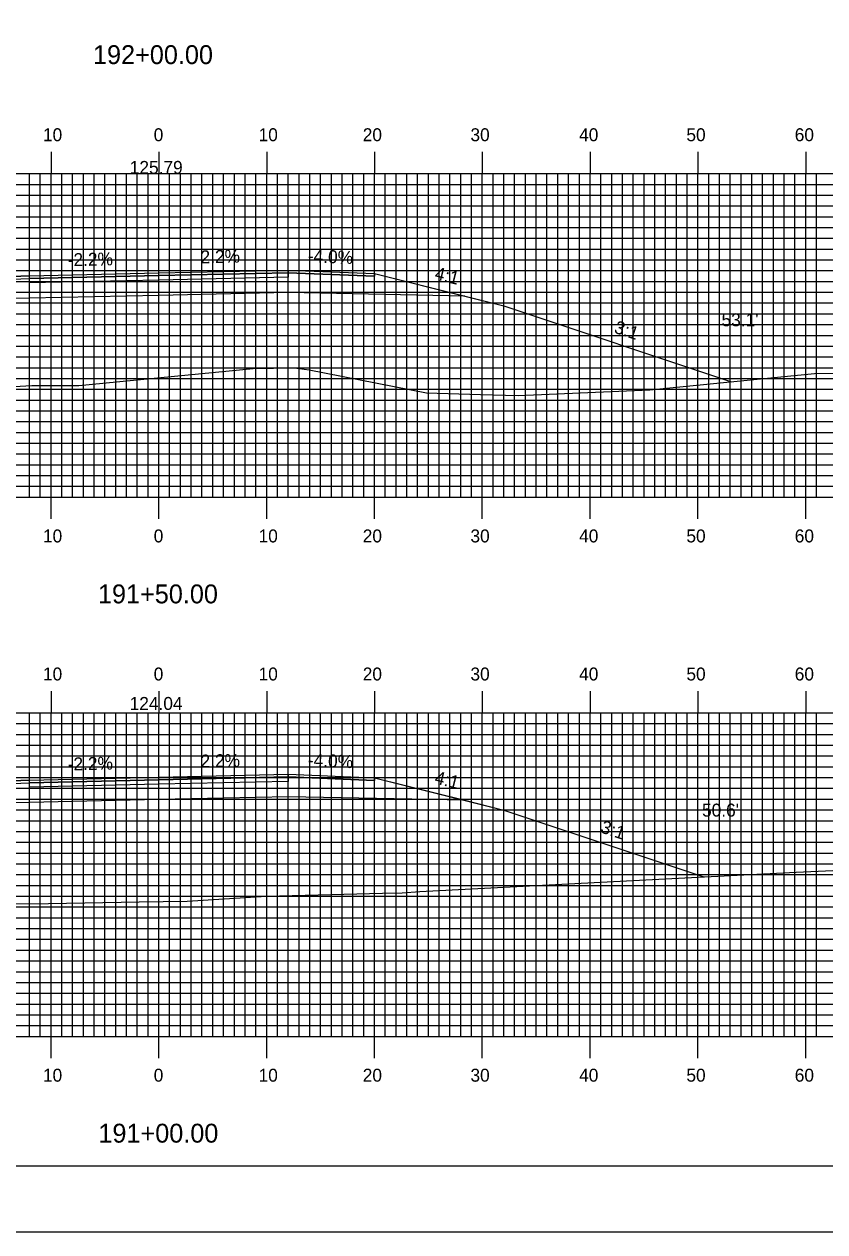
# Model space of a CAD drawing. Extents: x 1788550 to 1788893, y 442591 to 442811.
# Drawn here: x 1788703.1 to 1788777.4, y 442590.5 to 442702.5 of the extents above; entities that cross this region are included whole.
import ezdxf

# ---------------------------------------------------------------- set-up
doc = ezdxf.new("R2010")
doc.units = 0
for name, color, linetype in [('ANNOTATION', 7, 'Continuous'), ('BORDER', 7, 'Continuous'), ('D_Roadway_Centerline', 7, 'Continuous'), ('D_Roadway_Centerline_Text', 7, 'Continuous'), ('D_Roadway_Edge_Shoulder', 7, 'Continuous'), ('D_Roadway_Edge_TW', 7, 'Continuous'), ('D_Roadway_Pavement', 7, 'Continuous'), ('D_Roadway_SlopeLines', 7, 'Continuous'), ('D_Roadway_SubGrade', 7, 'Continuous'), ('D_Text_Standard', 7, 'Continuous'), ('H_V ANNOTATION', 7, 'Continuous'), ('MAJOR', 7, 'Continuous'), ('MINOR', 7, 'Continuous'), ('PLOT BOUNDARY', 7, 'Continuous'), ('S_Roadway_Centerline', 7, 'Continuous')]:
    doc.layers.add(name, color=color, linetype=linetype)

msp = doc.modelspace()

# ---------------------------------------------------------------- linework, layer by layer
at = {"layer": 'BORDER'}
msp.add_lwpolyline([(1788566.04, 442596.67), (1788886.04, 442596.67), (1788886.04, 442806.67), (1788566.04, 442806.67)], close=True, dxfattribs=at)
at = {"layer": 'D_Roadway_Centerline'}
for points in [[(1788655.04, 442666.34), (1788683.64, 442675.87), (1788687.28, 442676.78), (1788695.64, 442678.87), (1788703.64, 442679.19), (1788715.64, 442679.46), (1788727.64, 442679.72), (1788735.64, 442679.4), (1788744.01, 442677.31), (1788747.64, 442676.4), (1788768.74, 442669.37)], [(1788655.7, 442619.81), (1788683.64, 442629.12), (1788687.28, 442630.03), (1788695.64, 442632.12), (1788703.64, 442632.44), (1788715.64, 442632.71), (1788727.64, 442632.97), (1788735.64, 442632.65), (1788744.01, 442630.56), (1788747.64, 442629.65), (1788766.2, 442623.46)]]:
    msp.add_lwpolyline(points, dxfattribs=at)
at = {"layer": 'D_Roadway_Edge_Shoulder'}
for points in [[(1788727.64, 442679.72), (1788735.64, 442679.4), (1788735.64, 442679.15), (1788727.64, 442679.47)], [(1788703.64, 442679.19), (1788695.64, 442678.87), (1788695.64, 442678.62), (1788703.64, 442678.94)], [(1788727.64, 442632.97), (1788735.64, 442632.65), (1788735.64, 442632.4), (1788727.64, 442632.72)], [(1788703.64, 442632.44), (1788695.64, 442632.12), (1788695.64, 442631.87), (1788703.64, 442632.19)]]:
    msp.add_lwpolyline(points, close=True, dxfattribs=at)
at = {"layer": 'D_Roadway_Edge_TW'}
for points in [[(1788703.64, 442678.94), (1788703.64, 442679.19), (1788715.64, 442679.46), (1788727.64, 442679.72), (1788727.64, 442679.47), (1788715.64, 442679.21)], [(1788703.64, 442632.19), (1788703.64, 442632.44), (1788715.64, 442632.71), (1788727.64, 442632.97), (1788727.64, 442632.72), (1788715.64, 442632.46)]]:
    msp.add_lwpolyline(points, close=True, dxfattribs=at)
at = {"layer": 'D_Roadway_Pavement'}
for points in [[(1788703.64, 442678.53), (1788703.64, 442678.94), (1788715.64, 442679.21), (1788727.64, 442679.47), (1788727.64, 442679.05), (1788715.64, 442678.79)], [(1788703.64, 442631.78), (1788703.64, 442632.19), (1788715.64, 442632.46), (1788727.64, 442632.72), (1788727.64, 442632.3), (1788715.64, 442632.04)]]:
    msp.add_lwpolyline(points, close=True, dxfattribs=at)
at = {"layer": 'D_Roadway_SlopeLines'}
for points in [[(1788735.64, 442679.4), (1788747.64, 442676.4), (1788768.74, 442669.37)], [(1788735.64, 442632.65), (1788747.64, 442629.65), (1788766.2, 442623.46)]]:
    msp.add_lwpolyline(points, dxfattribs=at)
at = {"layer": 'D_Roadway_SubGrade'}
for points in [[(1788703.64, 442677.11), (1788687.28, 442676.78), (1788695.64, 442678.87), (1788695.64, 442678.62), (1788703.64, 442678.94), (1788715.64, 442679.21), (1788727.64, 442679.47), (1788735.64, 442679.15), (1788735.64, 442679.4), (1788744.01, 442677.31), (1788727.64, 442677.64), (1788715.64, 442677.37)], [(1788703.64, 442630.36), (1788687.28, 442630.03), (1788695.64, 442632.12), (1788695.64, 442631.87), (1788703.64, 442632.19), (1788715.64, 442632.46), (1788727.64, 442632.72), (1788735.64, 442632.4), (1788735.64, 442632.65), (1788744.01, 442630.56), (1788727.64, 442630.89), (1788715.64, 442630.62)]]:
    msp.add_lwpolyline(points, close=True, dxfattribs=at)
at = {"layer": 'MAJOR'}
for p, q in [((1788705.64, 442690.67), (1788705.64, 442688.67)), ((1788715.64, 442690.67), (1788715.64, 442688.67)), ((1788725.64, 442690.67), (1788725.64, 442688.67)), ((1788735.64, 442690.67), (1788735.64, 442688.67)), ((1788745.64, 442690.67), (1788745.64, 442688.67)), ((1788755.64, 442690.67), (1788755.64, 442688.67)), ((1788765.64, 442690.67), (1788765.64, 442688.67)), ((1788775.64, 442690.67), (1788775.64, 442688.67)), ((1788575.64, 442688.67), (1788855.64, 442688.67)), ((1788575.64, 442688.67), (1788855.64, 442688.67)), ((1788705.64, 442658.67), (1788705.64, 442688.67)), ((1788715.64, 442658.67), (1788715.64, 442688.67)), ((1788725.64, 442658.67), (1788725.64, 442688.67)), ((1788735.64, 442658.67), (1788735.64, 442688.67)), ((1788745.64, 442658.67), (1788745.64, 442688.67)), ((1788755.64, 442658.67), (1788755.64, 442688.67)), ((1788765.64, 442658.67), (1788765.64, 442688.67)), ((1788775.64, 442658.67), (1788775.64, 442688.67)), ((1788575.64, 442683.67), (1788855.64, 442683.67)), ((1788575.64, 442678.67), (1788855.64, 442678.67)), ((1788575.64, 442673.67), (1788855.64, 442673.67)), ((1788575.64, 442668.67), (1788855.64, 442668.67)), ((1788575.64, 442663.67), (1788855.64, 442663.67)), ((1788575.64, 442658.67), (1788855.64, 442658.67)), ((1788575.64, 442658.67), (1788855.64, 442658.67)), ((1788705.64, 442656.66), (1788705.64, 442658.67)), ((1788715.64, 442656.66), (1788715.64, 442658.67)), ((1788725.64, 442656.66), (1788725.64, 442658.67)), ((1788735.64, 442656.66), (1788735.64, 442658.67)), ((1788745.64, 442656.66), (1788745.64, 442658.67)), ((1788755.64, 442656.66), (1788755.64, 442658.67)), ((1788765.64, 442656.66), (1788765.64, 442658.67)), ((1788775.64, 442656.66), (1788775.64, 442658.67)), ((1788705.64, 442640.67), (1788705.64, 442638.67)), ((1788715.64, 442640.67), (1788715.64, 442638.67)), ((1788725.64, 442640.67), (1788725.64, 442638.67)), ((1788735.64, 442640.67), (1788735.64, 442638.67)), ((1788745.64, 442640.67), (1788745.64, 442638.67)), ((1788755.64, 442640.67), (1788755.64, 442638.67)), ((1788765.64, 442640.67), (1788765.64, 442638.67)), ((1788775.64, 442640.67), (1788775.64, 442638.67)), ((1788575.64, 442638.67), (1788855.64, 442638.67)), ((1788575.64, 442638.67), (1788855.64, 442638.67)), ((1788705.64, 442608.67), (1788705.64, 442638.67)), ((1788715.64, 442608.67), (1788715.64, 442638.67)), ((1788725.64, 442608.67), (1788725.64, 442638.67)), ((1788735.64, 442608.67), (1788735.64, 442638.67)), ((1788745.64, 442608.67), (1788745.64, 442638.67)), ((1788755.64, 442608.67), (1788755.64, 442638.67)), ((1788765.64, 442608.67), (1788765.64, 442638.67)), ((1788775.64, 442608.67), (1788775.64, 442638.67)), ((1788575.64, 442633.67), (1788855.64, 442633.67)), ((1788575.64, 442628.67), (1788855.64, 442628.67)), ((1788575.64, 442623.67), (1788855.64, 442623.67)), ((1788575.64, 442618.67), (1788855.64, 442618.67)), ((1788575.64, 442613.67), (1788855.64, 442613.67)), ((1788575.64, 442608.67), (1788855.64, 442608.67)), ((1788575.64, 442608.67), (1788855.64, 442608.67)), ((1788705.64, 442606.66), (1788705.64, 442608.67)), ((1788715.64, 442606.66), (1788715.64, 442608.67)), ((1788725.64, 442606.66), (1788725.64, 442608.67)), ((1788735.64, 442606.66), (1788735.64, 442608.67)), ((1788745.64, 442606.66), (1788745.64, 442608.67)), ((1788755.64, 442606.66), (1788755.64, 442608.67)), ((1788765.64, 442606.66), (1788765.64, 442608.67)), ((1788775.64, 442606.66), (1788775.64, 442608.67))]:
    msp.add_line(p, q, dxfattribs=at)
at = {"layer": 'MINOR'}
for p, q in [((1788703.64, 442658.67), (1788703.64, 442688.67)), ((1788704.64, 442658.67), (1788704.64, 442688.67)), ((1788706.64, 442658.67), (1788706.64, 442688.67)), ((1788707.64, 442658.67), (1788707.64, 442688.67)), ((1788708.64, 442658.67), (1788708.64, 442688.67)), ((1788709.64, 442658.67), (1788709.64, 442688.67)), ((1788710.64, 442658.67), (1788710.64, 442688.67)), ((1788711.64, 442658.67), (1788711.64, 442688.67)), ((1788712.64, 442658.67), (1788712.64, 442688.67)), ((1788713.64, 442658.67), (1788713.64, 442688.67)), ((1788714.64, 442658.67), (1788714.64, 442688.67)), ((1788716.64, 442658.67), (1788716.64, 442688.67)), ((1788717.64, 442658.67), (1788717.64, 442688.67)), ((1788718.64, 442658.67), (1788718.64, 442688.67)), ((1788719.64, 442658.67), (1788719.64, 442688.67)), ((1788720.64, 442658.67), (1788720.64, 442688.67)), ((1788721.64, 442658.67), (1788721.64, 442688.67)), ((1788722.64, 442658.67), (1788722.64, 442688.67)), ((1788723.64, 442658.67), (1788723.64, 442688.67)), ((1788724.64, 442658.67), (1788724.64, 442688.67)), ((1788726.64, 442658.67), (1788726.64, 442688.67)), ((1788727.64, 442658.67), (1788727.64, 442688.67)), ((1788728.64, 442658.67), (1788728.64, 442688.67)), ((1788729.64, 442658.67), (1788729.64, 442688.67)), ((1788730.64, 442658.67), (1788730.64, 442688.67)), ((1788731.64, 442658.67), (1788731.64, 442688.67)), ((1788732.64, 442658.67), (1788732.64, 442688.67)), ((1788733.64, 442658.67), (1788733.64, 442688.67)), ((1788734.64, 442658.67), (1788734.64, 442688.67)), ((1788736.64, 442658.67), (1788736.64, 442688.67)), ((1788737.64, 442658.67), (1788737.64, 442688.67)), ((1788738.64, 442658.67), (1788738.64, 442688.67)), ((1788739.64, 442658.67), (1788739.64, 442688.67)), ((1788740.64, 442658.67), (1788740.64, 442688.67)), ((1788741.64, 442658.67), (1788741.64, 442688.67)), ((1788742.64, 442658.67), (1788742.64, 442688.67)), ((1788743.64, 442658.67), (1788743.64, 442688.67)), ((1788744.64, 442658.67), (1788744.64, 442688.67)), ((1788746.64, 442658.67), (1788746.64, 442688.67)), ((1788747.64, 442658.67), (1788747.64, 442688.67)), ((1788748.64, 442658.67), (1788748.64, 442688.67)), ((1788749.64, 442658.67), (1788749.64, 442688.67)), ((1788750.64, 442658.67), (1788750.64, 442688.67)), ((1788751.64, 442658.67), (1788751.64, 442688.67)), ((1788752.64, 442658.67), (1788752.64, 442688.67)), ((1788753.64, 442658.67), (1788753.64, 442688.67)), ((1788754.64, 442658.67), (1788754.64, 442688.67)), ((1788756.64, 442658.67), (1788756.64, 442688.67)), ((1788757.64, 442658.67), (1788757.64, 442688.67)), ((1788758.64, 442658.67), (1788758.64, 442688.67)), ((1788759.64, 442658.67), (1788759.64, 442688.67)), ((1788760.64, 442658.67), (1788760.64, 442688.67)), ((1788761.64, 442658.67), (1788761.64, 442688.67)), ((1788762.64, 442658.67), (1788762.64, 442688.67)), ((1788763.64, 442658.67), (1788763.64, 442688.67)), ((1788764.64, 442658.67), (1788764.64, 442688.67)), ((1788766.64, 442658.67), (1788766.64, 442688.67)), ((1788767.64, 442658.67), (1788767.64, 442688.67)), ((1788768.64, 442658.67), (1788768.64, 442688.67)), ((1788769.64, 442658.67), (1788769.64, 442688.67)), ((1788770.64, 442658.67), (1788770.64, 442688.67)), ((1788771.64, 442658.67), (1788771.64, 442688.67)), ((1788772.64, 442658.67), (1788772.64, 442688.67)), ((1788773.64, 442658.67), (1788773.64, 442688.67)), ((1788774.64, 442658.67), (1788774.64, 442688.67)), ((1788776.64, 442658.67), (1788776.64, 442688.67)), ((1788575.64, 442687.67), (1788855.64, 442687.67)), ((1788575.64, 442686.67), (1788855.64, 442686.67)), ((1788575.64, 442685.67), (1788855.64, 442685.67)), ((1788575.64, 442684.67), (1788855.64, 442684.67)), ((1788575.64, 442682.67), (1788855.64, 442682.67)), ((1788575.64, 442681.67), (1788855.64, 442681.67)), ((1788575.64, 442680.67), (1788855.64, 442680.67)), ((1788575.64, 442679.67), (1788855.64, 442679.67)), ((1788575.64, 442677.67), (1788855.64, 442677.67)), ((1788575.64, 442676.67), (1788855.64, 442676.67)), ((1788575.64, 442675.67), (1788855.64, 442675.67)), ((1788575.64, 442674.67), (1788855.64, 442674.67)), ((1788575.64, 442672.67), (1788855.64, 442672.67)), ((1788575.64, 442671.67), (1788855.64, 442671.67)), ((1788575.64, 442670.67), (1788855.64, 442670.67)), ((1788575.64, 442669.67), (1788855.64, 442669.67)), ((1788575.64, 442667.67), (1788855.64, 442667.67)), ((1788575.64, 442666.67), (1788855.64, 442666.67)), ((1788575.64, 442665.67), (1788855.64, 442665.67)), ((1788575.64, 442664.67), (1788855.64, 442664.67)), ((1788575.64, 442662.67), (1788855.64, 442662.67)), ((1788575.64, 442661.67), (1788855.64, 442661.67)), ((1788575.64, 442660.67), (1788855.64, 442660.67)), ((1788575.64, 442659.67), (1788855.64, 442659.67)), ((1788703.64, 442608.67), (1788703.64, 442638.67)), ((1788704.64, 442608.67), (1788704.64, 442638.67)), ((1788706.64, 442608.67), (1788706.64, 442638.67)), ((1788707.64, 442608.67), (1788707.64, 442638.67)), ((1788708.64, 442608.67), (1788708.64, 442638.67)), ((1788709.64, 442608.67), (1788709.64, 442638.67)), ((1788710.64, 442608.67), (1788710.64, 442638.67)), ((1788711.64, 442608.67), (1788711.64, 442638.67)), ((1788712.64, 442608.67), (1788712.64, 442638.67)), ((1788713.64, 442608.67), (1788713.64, 442638.67)), ((1788714.64, 442608.67), (1788714.64, 442638.67)), ((1788716.64, 442608.67), (1788716.64, 442638.67)), ((1788717.64, 442608.67), (1788717.64, 442638.67)), ((1788718.64, 442608.67), (1788718.64, 442638.67)), ((1788719.64, 442608.67), (1788719.64, 442638.67)), ((1788720.64, 442608.67), (1788720.64, 442638.67)), ((1788721.64, 442608.67), (1788721.64, 442638.67)), ((1788722.64, 442608.67), (1788722.64, 442638.67)), ((1788723.64, 442608.67), (1788723.64, 442638.67)), ((1788724.64, 442608.67), (1788724.64, 442638.67)), ((1788726.64, 442608.67), (1788726.64, 442638.67)), ((1788727.64, 442608.67), (1788727.64, 442638.67)), ((1788728.64, 442608.67), (1788728.64, 442638.67)), ((1788729.64, 442608.67), (1788729.64, 442638.67)), ((1788730.64, 442608.67), (1788730.64, 442638.67)), ((1788731.64, 442608.67), (1788731.64, 442638.67)), ((1788732.64, 442608.67), (1788732.64, 442638.67)), ((1788733.64, 442608.67), (1788733.64, 442638.67)), ((1788734.64, 442608.67), (1788734.64, 442638.67)), ((1788736.64, 442608.67), (1788736.64, 442638.67)), ((1788737.64, 442608.67), (1788737.64, 442638.67)), ((1788738.64, 442608.67), (1788738.64, 442638.67)), ((1788739.64, 442608.67), (1788739.64, 442638.67)), ((1788740.64, 442608.67), (1788740.64, 442638.67)), ((1788741.64, 442608.67), (1788741.64, 442638.67)), ((1788742.64, 442608.67), (1788742.64, 442638.67)), ((1788743.64, 442608.67), (1788743.64, 442638.67)), ((1788744.64, 442608.67), (1788744.64, 442638.67)), ((1788746.64, 442608.67), (1788746.64, 442638.67)), ((1788747.64, 442608.67), (1788747.64, 442638.67)), ((1788748.64, 442608.67), (1788748.64, 442638.67)), ((1788749.64, 442608.67), (1788749.64, 442638.67)), ((1788750.64, 442608.67), (1788750.64, 442638.67)), ((1788751.64, 442608.67), (1788751.64, 442638.67)), ((1788752.64, 442608.67), (1788752.64, 442638.67)), ((1788753.64, 442608.67), (1788753.64, 442638.67)), ((1788754.64, 442608.67), (1788754.64, 442638.67)), ((1788756.64, 442608.67), (1788756.64, 442638.67)), ((1788757.64, 442608.67), (1788757.64, 442638.67)), ((1788758.64, 442608.67), (1788758.64, 442638.67)), ((1788759.64, 442608.67), (1788759.64, 442638.67)), ((1788760.64, 442608.67), (1788760.64, 442638.67)), ((1788761.64, 442608.67), (1788761.64, 442638.67)), ((1788762.64, 442608.67), (1788762.64, 442638.67)), ((1788763.64, 442608.67), (1788763.64, 442638.67)), ((1788764.64, 442608.67), (1788764.64, 442638.67)), ((1788766.64, 442608.67), (1788766.64, 442638.67)), ((1788767.64, 442608.67), (1788767.64, 442638.67)), ((1788768.64, 442608.67), (1788768.64, 442638.67)), ((1788769.64, 442608.67), (1788769.64, 442638.67)), ((1788770.64, 442608.67), (1788770.64, 442638.67)), ((1788771.64, 442608.67), (1788771.64, 442638.67)), ((1788772.64, 442608.67), (1788772.64, 442638.67)), ((1788773.64, 442608.67), (1788773.64, 442638.67)), ((1788774.64, 442608.67), (1788774.64, 442638.67)), ((1788776.64, 442608.67), (1788776.64, 442638.67)), ((1788575.64, 442637.67), (1788855.64, 442637.67)), ((1788575.64, 442636.67), (1788855.64, 442636.67)), ((1788575.64, 442635.67), (1788855.64, 442635.67)), ((1788575.64, 442634.67), (1788855.64, 442634.67)), ((1788575.64, 442632.67), (1788855.64, 442632.67)), ((1788575.64, 442631.67), (1788855.64, 442631.67)), ((1788575.64, 442630.67), (1788855.64, 442630.67)), ((1788575.64, 442629.67), (1788855.64, 442629.67)), ((1788575.64, 442627.67), (1788855.64, 442627.67)), ((1788575.64, 442626.67), (1788855.64, 442626.67)), ((1788575.64, 442625.67), (1788855.64, 442625.67)), ((1788575.64, 442624.67), (1788855.64, 442624.67)), ((1788575.64, 442622.67), (1788855.64, 442622.67)), ((1788575.64, 442621.67), (1788855.64, 442621.67)), ((1788575.64, 442620.67), (1788855.64, 442620.67)), ((1788575.64, 442619.67), (1788855.64, 442619.67)), ((1788575.64, 442617.67), (1788855.64, 442617.67)), ((1788575.64, 442616.67), (1788855.64, 442616.67)), ((1788575.64, 442615.67), (1788855.64, 442615.67)), ((1788575.64, 442614.67), (1788855.64, 442614.67)), ((1788575.64, 442612.67), (1788855.64, 442612.67)), ((1788575.64, 442611.67), (1788855.64, 442611.67)), ((1788575.64, 442610.67), (1788855.64, 442610.67)), ((1788575.64, 442609.67), (1788855.64, 442609.67))]:
    msp.add_line(p, q, dxfattribs=at)
at = {"layer": 'PLOT BOUNDARY'}
msp.add_lwpolyline([(1788549.86, 442590.55), (1788889.86, 442590.55), (1788889.86, 442810.55), (1788549.86, 442810.55)], close=True, dxfattribs=at)
at = {"layer": 'S_Roadway_Centerline'}
for points in [[(1788643.53, 442665.63), (1788653.56, 442666.27), (1788655.67, 442666.37), (1788659.7, 442666.44), (1788672.07, 442666.56), (1788694.58, 442668.49), (1788703.86, 442669.02), (1788708.21, 442669.03), (1788724.4, 442670.58), (1788728.18, 442670.65), (1788729.59, 442670.46), (1788740.45, 442668.35), (1788745.46, 442668.18), (1788748.96, 442668.08), (1788761.18, 442668.63), (1788764.27, 442668.92), (1788776.44, 442670.14), (1788784.84, 442670.21)], [(1788643.11, 442619.21), (1788653.38, 442619.7), (1788661.98, 442620.09), (1788665.4, 442620.21), (1788671.77, 442620.36), (1788677.48, 442620.47), (1788680.58, 442620.59), (1788689.42, 442620.71), (1788699.43, 442620.89), (1788701.49, 442620.95), (1788705.39, 442621), (1788713.8, 442621.15), (1788718.27, 442621.22), (1788725.62, 442621.67), (1788736.38, 442621.95), (1788738.22, 442621.99), (1788739.86, 442622.09), (1788762.01, 442623.25), (1788774.75, 442623.9), (1788786.36, 442624.41)]]:
    msp.add_lwpolyline(points, dxfattribs=at)

# ---------------------------------------------------------------- texts
at = {"layer": 'ANNOTATION'}
for s, rotation, p in [('-2.2%', 1.2603, (1788707.2, 442680.07)), ('2.2%', 1.2603, (1788719.52, 442680.34)), ('-4.0%', 357.7094, (1788729.44, 442680.45)), ('4:1', 345.9638, (1788741.15, 442678.89)), ('3:1', 341.5652, (1788757.79, 442673.93)), ('2.2%', 1.2603, (1788719.52, 442633.59)), ('-4.0%', 357.7094, (1788729.44, 442633.7)), ('-2.2%', 1.2603, (1788707.2, 442633.32)), ('4:1', 345.9638, (1788741.15, 442632.14)), ('3:1', 341.5652, (1788756.53, 442627.6))]:
    msp.add_text(s, height=1.2, rotation=rotation, dxfattribs=at).set_placement(p)
at = {"layer": 'D_Roadway_Centerline'}
for s, p in [('C', (1788715.64, 442679.46)), ('L', (1788715.64, 442679.45)), ('C', (1788715.64, 442632.71)), ('L', (1788715.64, 442632.7))]:
    msp.add_text(s, height=0.0146, dxfattribs=at).set_placement(p)
at = {"layer": 'D_Roadway_Centerline_Text'}
for s, p in [('125.79', (1788712.94, 442688.64)), ('124.04', (1788712.93, 442638.94))]:
    msp.add_text(s, height=1.2, dxfattribs=at).set_placement(p)
at = {"layer": 'D_Text_Standard'}
for s, p in [("53.1'", (1788767.83, 442674.51)), ("50.6'", (1788766.02, 442629.05))]:
    msp.add_text(s, height=1.2, dxfattribs=at).set_placement(p)
at = {"layer": 'H_V ANNOTATION'}
for s, height, p in [('192+00.00', 1.75, (1788709.53, 442698.82)), ('10', 1.2, (1788704.89, 442691.67)), ('0', 1.2, (1788715.16, 442691.67)), ('10', 1.2, (1788724.89, 442691.67)), ('20', 1.2, (1788734.55, 442691.67)), ('30', 1.2, (1788744.54, 442691.67)), ('40', 1.2, (1788754.62, 442691.67)), ('50', 1.2, (1788764.57, 442691.67)), ('60', 1.2, (1788774.62, 442691.67)), ('10', 1.2, (1788704.89, 442654.47)), ('0', 1.2, (1788715.16, 442654.47)), ('10', 1.2, (1788724.89, 442654.47)), ('20', 1.2, (1788734.55, 442654.47)), ('30', 1.2, (1788744.54, 442654.47)), ('40', 1.2, (1788754.62, 442654.47)), ('50', 1.2, (1788764.57, 442654.47)), ('60', 1.2, (1788774.62, 442654.47)), ('191+50.00', 1.75, (1788709.99, 442648.82)), ('10', 1.2, (1788704.89, 442641.67)), ('0', 1.2, (1788715.16, 442641.67)), ('10', 1.2, (1788724.89, 442641.67)), ('20', 1.2, (1788734.55, 442641.67)), ('30', 1.2, (1788744.54, 442641.67)), ('40', 1.2, (1788754.62, 442641.67)), ('50', 1.2, (1788764.57, 442641.67)), ('60', 1.2, (1788774.62, 442641.67)), ('10', 1.2, (1788704.89, 442604.47)), ('0', 1.2, (1788715.16, 442604.47)), ('10', 1.2, (1788724.89, 442604.47)), ('20', 1.2, (1788734.55, 442604.47)), ('30', 1.2, (1788744.54, 442604.47)), ('40', 1.2, (1788754.62, 442604.47)), ('50', 1.2, (1788764.57, 442604.47)), ('60', 1.2, (1788774.62, 442604.47)), ('191+00.00', 1.75, (1788710.03, 442598.82))]:
    msp.add_text(s, height=height, dxfattribs=at).set_placement(p)

doc.saveas('drawing.dxf')
